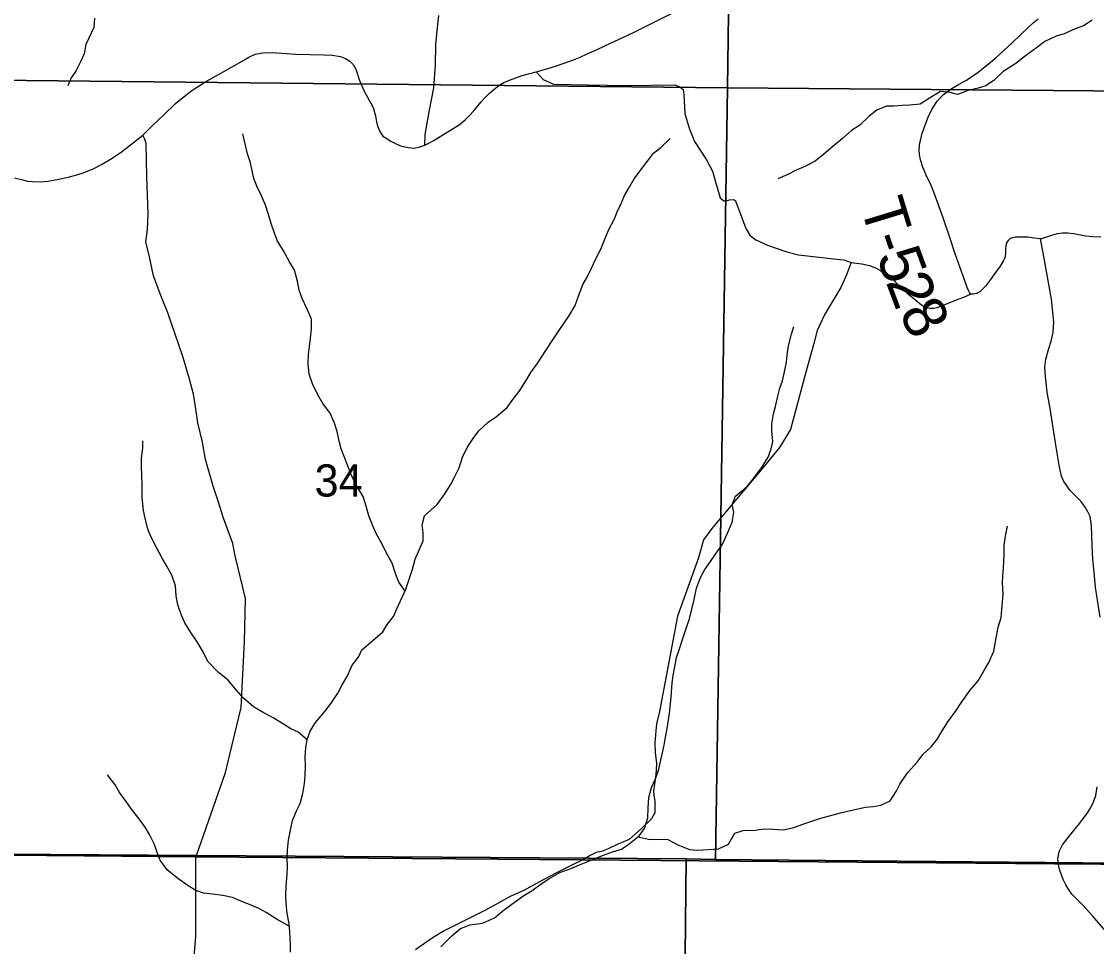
# Model space of a CAD drawing. Extents: x 0 to 191, y 0 to 55.
# Drawn here: x 145.059 to 145.758, y 20.779 to 21.382 of the extents above; entities that cross this region are included whole.
import ezdxf

# ---------------------------------------------------------------- set-up
doc = ezdxf.new("R2010")
doc.units = 0
for name, color, linetype in [('GM_X_Corporation', 7, 'Continuous'), ('GM_X_County_Road', 7, 'Continuous'), ('GM_X_Minor_River', 7, 'Continuous'), ('GM_X_Section_Text', 7, 'Continuous'), ('GM_X_Township_Road', 7, 'Continuous'), ('GM_X_Township_Road_Text', 7, 'Continuous')]:
    doc.layers.add(name, color=color, linetype=linetype)

msp = doc.modelspace()

# ---------------------------------------------------------------- linework, layer by layer
at = {"layer": 'GM_X_Corporation'}
for points in [[(146.52877, 22.67924), (146.52412, 22.06864), (146.52059, 21.60574), (146.51644, 21.08296), (146.51644, 21.08173), (146.51664, 20.82724), (146.47837, 20.82755), (146.47724, 20.82756), (146.44015, 20.82784), (146.43784, 20.82786), (146.12204, 20.83034), (146.12018, 20.83035), (145.73354, 20.83338), (145.73117, 20.8334), (145.42327, 20.83582), (145.34145, 20.83646), (145.17243, 20.8379), (145.0026, 20.83935)], [(145.0026, 20.83935), (145.17243, 20.8379), (145.34145, 20.83646), (145.42327, 20.83582), (145.73117, 20.8334), (145.73354, 20.83338), (146.12018, 20.83035), (146.12204, 20.83034), (146.43784, 20.82786), (146.44015, 20.82784), (146.47724, 20.82756), (146.47837, 20.82755), (146.51664, 20.82724), (146.51644, 21.08173), (146.51644, 21.08296), (146.52059, 21.60574), (146.52412, 22.06864), (146.74796, 22.06495), (146.94723, 22.06204), (146.94931, 22.06201), (147.41583, 22.05521)]]:
    msp.add_lwpolyline(points, dxfattribs=at)
for points in [[(145.02504, 21.84324), (145.52496, 21.8368), (145.51832, 21.3384), (145.0205, 21.34372)], [(145.52496, 21.8368), (146.02436, 21.83663), (146.02149, 21.33428), (145.51832, 21.3384)], [(145.51832, 21.3384), (145.5104, 20.8362), (145.49144, 20.83655), (145.01412, 20.83983), (145.0205, 21.34372)], [(145.51832, 21.3384), (146.02149, 21.33428), (146.01219, 20.83147), (145.5104, 20.8362)], [(145.00275, 20.8397), (145.01412, 20.83983), (145.49144, 20.83655), (145.48618, 20.33399), (144.99311, 20.33823)], [(145.5104, 20.8362), (146.01219, 20.83147), (146.00519, 20.32717), (145.48618, 20.33399), (145.49144, 20.83655)]]:
    msp.add_lwpolyline(points, close=True, dxfattribs=at)
at = {"layer": 'GM_X_County_Road'}
msp.add_lwpolyline([(145.05456, 21.27986), (145.05991, 21.2785), (145.06282, 21.27772), (145.0662, 21.27734), (145.07129, 21.27731), (145.07611, 21.2777), (145.08212, 21.27872), (145.09021, 21.28058), (145.09503, 21.28177), (145.09971, 21.28326), (145.10561, 21.28576), (145.11101, 21.2885), (145.11691, 21.29193), (145.1238, 21.2965), (145.13796, 21.30755), (145.14352, 21.31315), (145.15172, 21.32107), (145.15925, 21.32821), (145.16474, 21.33287), (145.16989, 21.33669), (145.17837, 21.34217), (145.19764, 21.35303), (145.20412, 21.35674), (145.20689, 21.3584), (145.21105, 21.36029), (145.21603, 21.36123), (145.22213, 21.36139), (145.23752, 21.3604), (145.25575, 21.3599), (145.26112, 21.35957), (145.26644, 21.35874), (145.26987, 21.35757), (145.27264, 21.35585), (145.2748, 21.35369), (145.27646, 21.35054), (145.27901, 21.34311), (145.28162, 21.33669), (145.28776, 21.3255), (145.28937, 21.32029), (145.29004, 21.31636), (145.2907, 21.31354), (145.29225, 21.30949), (145.29419, 21.307), (145.29635, 21.30556), (145.29929, 21.30362), (145.30316, 21.30168), (145.30616, 21.30035), (145.31059, 21.29947), (145.31457, 21.29924), (145.31823, 21.29991), (145.32133, 21.30107), (145.32449, 21.30262), (145.32754, 21.30428), (145.34377, 21.31426), (145.3477, 21.31747), (145.35069, 21.32063), (145.3539, 21.32428), (145.358, 21.32932), (145.36016, 21.33176), (145.36338, 21.33486), (145.3662, 21.33741), (145.36963, 21.33985), (145.3729, 21.34179), (145.37645, 21.3435), (145.3847, 21.34644), (145.39384, 21.34888), (145.40148, 21.35098), (145.4065, 21.3525), (145.41204, 21.35438), (145.41806, 21.35673), (145.42248, 21.35847), (145.42708, 21.36054), (145.43258, 21.36289), (145.4386, 21.36571), (145.45712, 21.3745), (145.47107, 21.38145), (145.49265, 21.39212)], dxfattribs=at)
at = {"layer": 'GM_X_Minor_River'}
for points in [[(145.10647, 21.38384), (145.10616, 21.37758), (145.10078, 21.36653), (145.09971, 21.36064), (145.0973, 21.3553), (145.09452, 21.34978), (145.09135, 21.34481), (145.08913, 21.33967)], [(145.75551, 21.38245), (145.74987, 21.37879), (145.7444, 21.37684), (145.73724, 21.37354), (145.73214, 21.37197), (145.72479, 21.36867), (145.71934, 21.36445), (145.7122, 21.35926), (145.70525, 21.35388), (145.69773, 21.34906), (145.69173, 21.34331), (145.68646, 21.33966), (145.68137, 21.33828), (145.67494, 21.3367), (145.66796, 21.33416), (145.66322, 21.33544), (145.65678, 21.33594), (145.65038, 21.33209), (145.64361, 21.32785), (145.63699, 21.32721), (145.63207, 21.32697), (145.62658, 21.32654), (145.62166, 21.32649), (145.61544, 21.32396), (145.61037, 21.31993), (145.60437, 21.31418), (145.59891, 21.31071), (145.5931, 21.30534), (145.5869, 21.30016), (145.58108, 21.29517), (145.57545, 21.29075), (145.56829, 21.28708), (145.56264, 21.28456), (145.55755, 21.28204), (145.55114, 21.27913)], [(145.30855, 21.01086), (145.30448, 21.01667), (145.30254, 21.02158), (145.30019, 21.02896), (145.29652, 21.03555), (145.29382, 21.04103), (145.28977, 21.04838), (145.28763, 21.05329), (145.28492, 21.05971), (145.28334, 21.06614), (145.28119, 21.07237), (145.27656, 21.08029), (145.27328, 21.08708), (145.27133, 21.09237), (145.269, 21.09842), (145.26705, 21.10352), (145.26567, 21.10843), (145.26429, 21.11468), (145.26271, 21.12016), (145.25981, 21.12658), (145.25501, 21.13297), (145.25173, 21.13863), (145.24825, 21.1458), (145.24611, 21.15204), (145.24547, 21.15885), (145.24579, 21.16493), (145.2463, 21.17005), (145.247, 21.17537), (145.2477, 21.18163), (145.24763, 21.18789), (145.24492, 21.19431), (145.24163, 21.20129), (145.23968, 21.20677), (145.23848, 21.21263), (145.23671, 21.21963), (145.23343, 21.2251), (145.22919, 21.23264), (145.22553, 21.23867), (145.22359, 21.24377), (145.22163, 21.24944), (145.21948, 21.25662), (145.21772, 21.2621), (145.2152, 21.26814), (145.2123, 21.27399), (145.21016, 21.27947), (145.20897, 21.28439), (145.20797, 21.28949), (145.20602, 21.29554), (145.20444, 21.30197), (145.20305, 21.30841)], [(145.41926, 21.19683), (145.42148, 21.20273), (145.42424, 21.21035), (145.42721, 21.21568), (145.42999, 21.2214), (145.4324, 21.22673), (145.43593, 21.23341), (145.43851, 21.23988), (145.4411, 21.24616), (145.44482, 21.25303), (145.44647, 21.25778), (145.44925, 21.2635), (145.45129, 21.26826), (145.45426, 21.2736), (145.45761, 21.27913), (145.46266, 21.28582), (145.46621, 21.29078), (145.47013, 21.29594), (145.47501, 21.2996), (145.48101, 21.30534)], [(145.23405, 20.77588), (145.234, 20.781), (145.23354, 20.78877), (145.2331, 20.79427), (145.2319, 20.80089), (145.23126, 20.80753), (145.23102, 20.81264), (145.23115, 20.81852), (145.23183, 20.82649), (145.23216, 20.83124), (145.23191, 20.83712), (145.23205, 20.84224), (145.23274, 20.84869), (145.23417, 20.85629), (145.23526, 20.86142), (145.23784, 20.8679), (145.24025, 20.87266), (145.24208, 20.87913), (145.24315, 20.88559), (145.24348, 20.8909), (145.24379, 20.89735), (145.24354, 20.90304), (145.24405, 20.90873), (145.24494, 20.91424), (145.24678, 20.91957), (145.25032, 20.92529), (145.2563, 20.93237), (145.26041, 20.93791), (145.26489, 20.9444), (145.26768, 20.94974), (145.27084, 20.95527), (145.27417, 20.9627), (145.27828, 20.96786), (145.28051, 20.97263), (145.28764, 20.97877), (145.29402, 20.98433), (145.29681, 20.9891), (145.30092, 20.99426), (145.30314, 20.99921), (145.30685, 21.00722), (145.30907, 21.01198), (145.31329, 21.02511), (145.31512, 21.03157), (145.3203, 21.04357), (145.32024, 21.04869), (145.31962, 21.05399), (145.32127, 21.05989), (145.32933, 21.06717), (145.33437, 21.07424), (145.3381, 21.07997), (145.3407, 21.08492), (145.34367, 21.09102), (145.34587, 21.09806), (145.34902, 21.10435), (145.35275, 21.11026), (145.35648, 21.11523), (145.36267, 21.12079), (145.36794, 21.12445), (145.37488, 21.1304), (145.37862, 21.13556), (145.38273, 21.14072), (145.38757, 21.14835), (145.39037, 21.15312), (145.39447, 21.15885), (145.40063, 21.16801), (145.40379, 21.17297), (145.40771, 21.17889), (145.41181, 21.185), (145.41498, 21.18977), (145.41926, 21.19683)], [(145.33171, 20.77934), (145.33902, 20.78644), (145.34465, 20.79123), (145.35087, 20.79357), (145.35901, 20.7946), (145.36673, 20.7981), (145.3733, 20.80347), (145.3795, 20.80809), (145.38589, 20.8127), (145.39116, 20.81598), (145.39718, 20.82021), (145.40282, 20.82388), (145.40922, 20.82773), (145.41639, 20.83027), (145.42317, 20.83299), (145.43071, 20.83611), (145.4358, 20.83824), (145.44354, 20.84117), (145.44939, 20.84274), (145.45428, 20.84621), (145.46085, 20.85158), (145.46421, 20.85636), (145.46641, 20.86321), (145.46672, 20.86985), (145.46722, 20.87649), (145.46886, 20.88295), (145.47145, 20.88867), (145.47366, 20.89495), (145.47474, 20.89989), (145.47583, 20.90464), (145.4771, 20.91053), (145.47799, 20.91566), (145.47907, 20.92136), (145.48067, 20.93105), (145.4817, 20.94168), (145.48236, 20.95117), (145.48288, 20.95591), (145.48396, 20.96142), (145.48503, 20.9675), (145.48687, 20.97264), (145.48926, 20.98006), (145.49183, 20.98786), (145.49367, 20.99281), (145.49657, 21.00535), (145.4982, 21.01276), (145.50078, 21.01961), (145.50357, 21.02495), (145.5073, 21.03011), (145.51047, 21.03488), (145.51514, 21.04138), (145.51828, 21.04861), (145.52143, 21.05566), (145.5225, 21.06231), (145.52131, 21.06722), (145.52353, 21.07256), (145.53104, 21.07889), (145.53534, 21.08424), (145.54038, 21.09112), (145.54466, 21.09799), (145.54669, 21.10332), (145.54778, 21.10826), (145.54714, 21.11489), (145.54709, 21.11963), (145.54816, 21.12628), (145.54944, 21.13103), (145.55107, 21.13768), (145.55235, 21.14282), (145.554, 21.14776), (145.55546, 21.15347), (145.55672, 21.15992), (145.55741, 21.16638), (145.55811, 21.17131), (145.55994, 21.17797), (145.5614, 21.1831)], [(145.24489, 20.91394), (145.23902, 20.91911), (145.23427, 20.92115), (145.2295, 20.92413), (145.22265, 20.92824), (145.21617, 20.93177), (145.20989, 20.9355), (145.20339, 20.94112), (145.19898, 20.94639), (145.19324, 20.95297), (145.18713, 20.95783), (145.18024, 20.96497), (145.17772, 20.97044), (145.17368, 20.97723), (145.16925, 20.98382), (145.16521, 20.99023), (145.16289, 20.9957), (145.16074, 21.00194), (145.15973, 21.00781), (145.15929, 21.01425), (145.15675, 21.02124), (145.15348, 21.02708), (145.15058, 21.03236), (145.14653, 21.03953), (145.14324, 21.04632), (145.1413, 21.05123), (145.13953, 21.05823), (145.13834, 21.06334), (145.13749, 21.07167), (145.13742, 21.07907), (145.13734, 21.08646), (145.1371, 21.09177), (145.13704, 21.09746), (145.13792, 21.10391), (145.13787, 21.10865)], [(145.45991, 20.85081), (145.46807, 20.84919), (145.4745, 20.84945), (145.47943, 20.84912), (145.4859, 20.84558), (145.49351, 20.84262), (145.49881, 20.84211), (145.51244, 20.843), (145.51903, 20.84611), (145.52312, 20.85316), (145.52841, 20.85492), (145.53635, 20.85519), (145.54146, 20.856), (145.5479, 20.85588), (145.55472, 20.85538), (145.56152, 20.85697), (145.56736, 20.85911), (145.57378, 20.86126), (145.57906, 20.86302), (145.58699, 20.86519), (145.5919, 20.86657), (145.60116, 20.86856), (145.60815, 20.87014), (145.61307, 20.87057), (145.61798, 20.87138), (145.6242, 20.87429), (145.62811, 20.8804), (145.63033, 20.88516), (145.63537, 20.89261), (145.64174, 20.8995), (145.64566, 20.90466), (145.65091, 20.90945), (145.65502, 20.91461), (145.658, 20.91995), (145.66173, 20.92568), (145.66714, 20.93313), (145.67031, 20.93809), (145.67609, 20.9463), (145.68133, 20.95242), (145.68561, 20.95967), (145.68822, 20.96444), (145.69155, 20.97168), (145.6928, 20.97909), (145.69442, 20.98726), (145.69625, 20.99372), (145.69676, 20.99885), (145.69728, 21.00359), (145.69761, 21.0089), (145.69716, 21.01592), (145.69748, 21.02085), (145.69781, 21.02597), (145.69829, 21.03432), (145.69823, 21.04077), (145.69948, 21.04779), (145.70056, 21.05311)], [(145.23323, 20.79273), (145.22531, 20.79703), (145.21826, 20.8017), (145.2135, 20.80412), (145.20742, 20.8069), (145.20133, 20.80931), (145.19639, 20.81134), (145.18994, 20.81279), (145.1833, 20.81348), (145.17743, 20.81418), (145.17249, 20.81603), (145.16734, 20.81901), (145.16067, 20.82368), (145.15379, 20.82949), (145.14919, 20.8357), (145.14724, 20.84061), (145.14548, 20.84591), (145.1422, 20.85232), (145.1395, 20.85722), (145.13547, 20.86249), (145.13067, 20.86889), (145.12702, 20.87397), (145.1228, 20.87981), (145.11991, 20.88471), (145.11492, 20.8913)]]:
    msp.add_lwpolyline(points, dxfattribs=at)
at = {"layer": 'GM_X_Township_Road'}
for points in [[(145.32133, 21.30107), (145.32171, 21.30813), (145.32424, 21.32285), (145.32716, 21.33833), (145.32842, 21.35309), (145.32842, 21.35795), (145.32846, 21.36158), (145.32866, 21.36656), (145.32988, 21.37982), (145.33055, 21.38543)], [(145.7219, 21.24021), (145.71799, 21.24065), (145.71375, 21.24111), (145.70854, 21.2412), (145.70551, 21.24114), (145.70354, 21.24083), (145.70227, 21.24026), (145.70111, 21.23926), (145.70002, 21.23793), (145.69936, 21.2355), (145.69921, 21.23344), (145.69924, 21.23096), (145.6989, 21.22841), (145.6983, 21.22687), (145.69763, 21.22559), (145.69566, 21.22241), (145.69263, 21.21811), (145.68942, 21.21371), (145.68608, 21.20941), (145.68378, 21.20687), (145.68254, 21.20565), (145.68024, 21.20456), (145.67824, 21.20408), (145.67648, 21.20405), (145.67578, 21.20514), (145.67518, 21.20641), (145.67414, 21.20849), (145.67199, 21.21475), (145.66971, 21.22115), (145.66633, 21.23031), (145.6629, 21.2409), (145.65862, 21.25377), (145.65319, 21.26878), (145.65051, 21.27547), (145.64831, 21.28015), (145.64538, 21.2868), (145.6438, 21.29161), (145.64315, 21.29496), (145.6431, 21.29857), (145.6435, 21.30252), (145.64398, 21.30508), (145.64506, 21.30881), (145.64889, 21.31932), (145.65144, 21.32477), (145.65474, 21.32968), (145.65888, 21.33408), (145.66378, 21.33769), (145.66858, 21.34064), (145.67371, 21.3435), (145.68147, 21.3486), (145.68713, 21.35311), (145.69285, 21.35803), (145.70355, 21.36765), (145.71401, 21.37774), (145.71722, 21.38066), (145.72047, 21.38332)], [(145.39384, 21.34888), (145.39833, 21.34383), (145.4052, 21.3409), (145.42725, 21.34042), (145.45286, 21.33984), (145.48396, 21.34044), (145.48738, 21.33914), (145.48948, 21.33726), (145.48988, 21.33403), (145.49054, 21.3217), (145.49346, 21.31205), (145.49674, 21.30353), (145.50461, 21.29144), (145.50864, 21.28407), (145.51098, 21.27574), (145.51351, 21.26684), (145.51599, 21.26496), (145.51751, 21.26478), (145.51959, 21.26555), (145.52243, 21.26576), (145.52357, 21.26482), (145.53015, 21.24684), (145.53284, 21.24249), (145.53628, 21.23967), (145.54427, 21.23593), (145.55682, 21.23165), (145.56442, 21.22962), (145.59138, 21.22658), (145.59394, 21.22643), (145.59878, 21.2248)], [(145.17288, 20.83864), (145.19167, 20.89282), (145.20199, 20.93503), (145.20415, 20.97793), (145.20474, 21.00597), (145.19806, 21.03368), (145.19649, 21.04183), (145.1904, 21.05824), (145.18686, 21.06944), (145.18362, 21.07907), (145.1788, 21.09646), (145.17684, 21.10776), (145.1737, 21.12043), (145.17193, 21.13232), (145.17085, 21.139), (145.16829, 21.14882), (145.16407, 21.16356), (145.15424, 21.19185), (145.14933, 21.20423), (145.14491, 21.21612), (145.14236, 21.2284), (145.14, 21.23822), (145.14108, 21.24589), (145.14147, 21.25669), (145.14051, 21.28053), (145.1401, 21.30218), (145.13931, 21.30493), (145.13796, 21.30755)], [(145.76069, 20.99391), (145.75782, 21.01349), (145.75653, 21.02536), (145.75593, 21.03164), (145.75555, 21.04064), (145.75517, 21.05334), (145.75419, 21.05939), (145.75283, 21.06249), (145.75094, 21.06552), (145.74807, 21.0693), (145.74118, 21.07641), (145.73713, 21.08225), (145.73559, 21.08556), (145.734, 21.09289), (145.73211, 21.10446), (145.72818, 21.12972), (145.72636, 21.1403), (145.72523, 21.15059), (145.7247, 21.15656), (145.72531, 21.16185), (145.72735, 21.16873), (145.72893, 21.1735), (145.73014, 21.1794), (145.73067, 21.18582), (145.72916, 21.20087), (145.72405, 21.22859), (145.7219, 21.24021), (145.72921, 21.2425), (145.73305, 21.2435), (145.73622, 21.24408), (145.7396, 21.24408), (145.74369, 21.24356), (145.75148, 21.24202), (145.75608, 21.24153), (145.76114, 21.24147)], [(145.59878, 21.2248), (145.59566, 21.21658), (145.59212, 21.2084), (145.58157, 21.19103), (145.57666, 21.18049), (145.57438, 21.172), (145.57178, 21.16264), (145.56844, 21.15017)], [(145.59878, 21.2248), (145.60572, 21.22387), (145.61063, 21.22284), (145.61463, 21.2212), (145.61781, 21.21953), (145.62512, 21.21441), (145.6299, 21.20962), (145.63496, 21.20507), (145.6446, 21.19726), (145.64775, 21.19529), (145.6499, 21.1949), (145.65233, 21.19505), (145.65466, 21.1955), (145.6593, 21.19708), (145.66724, 21.20036), (145.67216, 21.2021), (145.67648, 21.20405)], [(145.56844, 21.15017), (145.5593, 21.11602), (145.5522, 21.10423), (145.54232, 21.09227), (145.50817, 21.05154), (145.50262, 21.04409), (145.4995, 21.03247), (145.48573, 20.99459), (145.47402, 20.9325), (145.47212, 20.92447), (145.47158, 20.91981), (145.47103, 20.91216), (145.47136, 20.90559), (145.47218, 20.89875), (145.47199, 20.89422), (145.47145, 20.88956), (145.47023, 20.88074), (145.47034, 20.87793), (145.47097, 20.87411), (145.47112, 20.86649), (145.4688, 20.86254), (145.46235, 20.85635), (145.45814, 20.85269), (145.45426, 20.84924), (145.45015, 20.84735), (145.4469, 20.84608), (145.44059, 20.84315), (145.43626, 20.84122), (145.43383, 20.84094), (145.43286, 20.84068), (145.42948, 20.83886), (145.4284, 20.83821), (145.42731, 20.83756), (145.42337, 20.83555), (145.41875, 20.83319), (145.40662, 20.82714), (145.39598, 20.82157), (145.38571, 20.81596), (145.37739, 20.81221), (145.37111, 20.80868), (145.37049, 20.80835)], [(145.73347, 20.83462), (145.73324, 20.83663), (145.73415, 20.84139), (145.73619, 20.8457), (145.74073, 20.85152), (145.74754, 20.85984), (145.75245, 20.86642), (145.75442, 20.86952), (145.75665, 20.87403), (145.75797, 20.87769), (145.7588, 20.88351)], [(145.15892, 20.70703), (145.16693, 20.72089), (145.17253, 20.78584), (145.17253, 20.83763), (145.17271, 20.83814), (145.17288, 20.83864)], [(145.7641, 20.7899), (145.75601, 20.79927), (145.7495, 20.8063), (145.74232, 20.81349), (145.74013, 20.81681), (145.73861, 20.81923), (145.73695, 20.82256), (145.73521, 20.82725), (145.73415, 20.8305), (145.73364, 20.83312), (145.73347, 20.83462)], [(145.37049, 20.80835), (145.36054, 20.80303), (145.34176, 20.79354), (145.33397, 20.7896), (145.32673, 20.78535), (145.31846, 20.77953), (145.31538, 20.77725)]]:
    msp.add_lwpolyline(points, dxfattribs=at)

# ---------------------------------------------------------------- texts
at = {"layer": 'GM_X_Section_Text'}
msp.add_text('34', height=0.020928, rotation=0.00001, dxfattribs=at).set_placement((145.2497, 21.07237))
at = {"layer": 'GM_X_Township_Road_Text'}
for s, rotation, p in [('T', 286.96977, (145.60449, 21.26184)), ('-', 288.91219, (145.61102, 21.24052)), ('5', 290.16708, (145.61503, 21.22884)), ('2', 290.52523, (145.62113, 21.21224)), ('8', 299.33308, (145.62927, 21.19153))]:
    msp.add_text(s, height=0.02841, rotation=rotation, dxfattribs=at).set_placement(p)

doc.saveas('drawing.dxf')
